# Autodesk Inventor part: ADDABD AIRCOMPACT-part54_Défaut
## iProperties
Shininess: 64.0
Length Units: 11269
Angle Units: 11279
Time Units: 11290
Mass Units: 11283
Length Display Precision: 3
Angle Display Precision: 2
Compacted: True
Part Number: ADDABD AIRCOMPACT-part54_Défaut
Document SubType Name: Modeling
Created: 2006-01
Material: Par défaut
Designer: riri
Density: 0.0
Volumn: 0.0
Area: 0.0
PropertySet Name: Model Information
Control State: 0
Master: False
Checked Out: False
Author: riri
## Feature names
1. Base1
